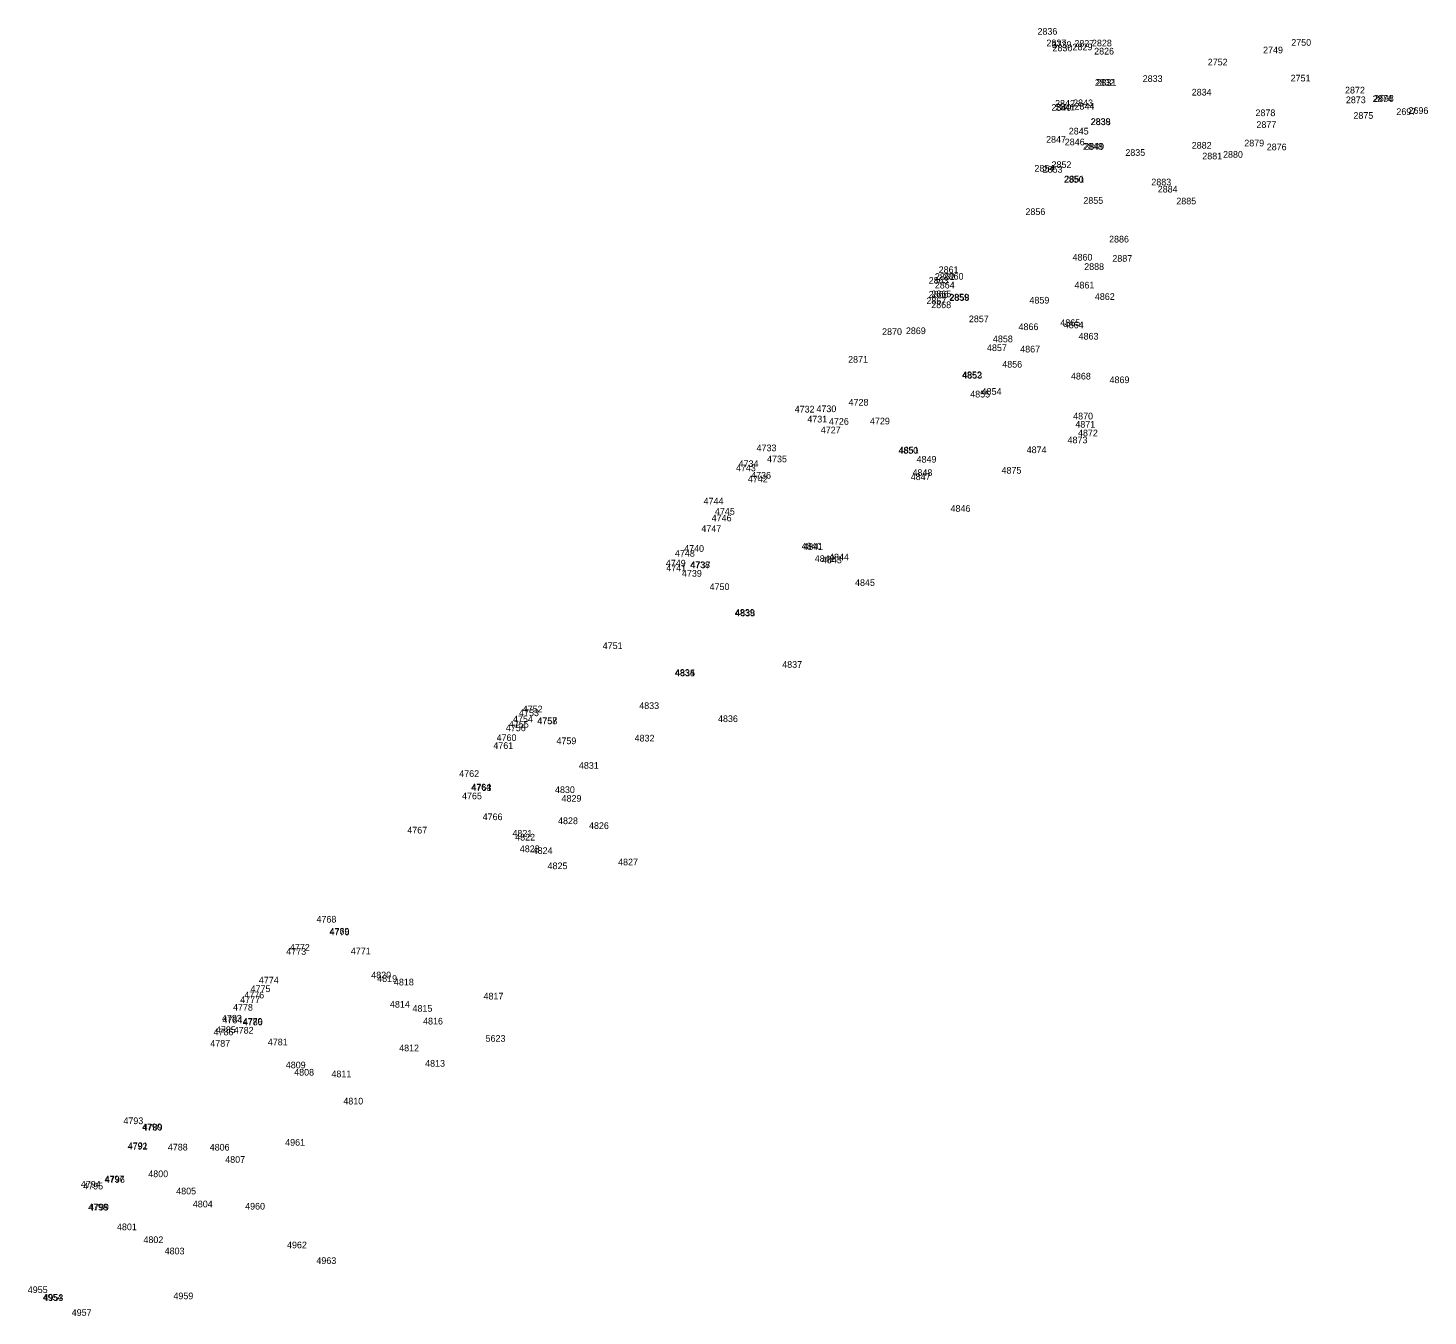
# Model space of a CAD drawing. Extents: x -740053 to -737517, y -1033516 to -1032476.
# Drawn here: x -738879 to -738763.6, y -1032731.7 to -1032625.6 of the extents above; entities that cross this region are included whole.
import ezdxf

# ---------------------------------------------------------------- set-up
doc = ezdxf.new("R2010")
doc.units = 0
doc.layers.add('bod-cislo', color=7, linetype='Continuous')

msp = doc.modelspace()

# ---------------------------------------------------------------- texts
at = {"layer": 'bod-cislo'}
for s, p in [('2836', (-738795.8, -1032626.13)), ('2837', (-738795.06, -1032627.08)), ('3739', (-738794.63, -1032627.22)), ('2830', (-738794.56, -1032627.49)), ('2829', (-738792.91, -1032627.41)), ('2827', (-738792.76, -1032627.12)), ('2828', (-738791.31, -1032627.09)), ('2826', (-738791.13, -1032627.76)), ('2749', (-738777.21, -1032627.66)), ('2750', (-738774.89, -1032627.04)), ('2752', (-738781.77, -1032628.66)), ('2833', (-738787.13, -1032630.02)), ('2751', (-738774.94, -1032629.98)), ('2832', (-738791.07, -1032630.33)), ('2831', (-738790.94, -1032630.34)), ('2834', (-738783.09, -1032631.14)), ('2872', (-738770.46, -1032630.97)), ('2840', (-738794.65, -1032632.4)), ('2842', (-738794.35, -1032632.06)), ('2841', (-738794.33, -1032632.36)), ('2843', (-738792.86, -1032632.02)), ('2844', (-738792.75, -1032632.3)), ('2873', (-738770.39, -1032631.77)), ('2874', (-738768.19, -1032631.68)), ('2698', (-738768.08, -1032631.64)), ('2839', (-738791.42, -1032633.56)), ('2838', (-738791.4, -1032633.58)), ('2878', (-738777.84, -1032632.84)), ('2875', (-738769.77, -1032633.06)), ('2697', (-738766.23, -1032632.74)), ('2696', (-738765.23, -1032632.65)), ('2845', (-738793.22, -1032634.35)), ('2877', (-738777.76, -1032633.81)), ('2847', (-738795.09, -1032635.03)), ('2846', (-738793.55, -1032635.24)), ('2848', (-738792.05, -1032635.6)), ('2849', (-738791.95, -1032635.61)), ('2882', (-738783.09, -1032635.52)), ('2879', (-738778.76, -1032635.33)), ('2876', (-738776.91, -1032635.65)), ('2852', (-738794.64, -1032637.11)), ('2835', (-738788.56, -1032636.11)), ('2881', (-738782.22, -1032636.4)), ('2880', (-738780.51, -1032636.27)), ('2854', (-738796.05, -1032637.41)), ('2853', (-738795.37, -1032637.5)), ('2850', (-738793.63, -1032638.33)), ('2851', (-738793.58, -1032638.29)), ('2883', (-738786.42, -1032638.54)), ('2884', (-738785.89, -1032639.13)), ('2855', (-738792.02, -1032640.06)), ('2885', (-738784.36, -1032640.11)), ('2856', (-738796.79, -1032640.99)), ('2886', (-738789.9, -1032643.25)), ('4860', (-738792.91, -1032644.74)), ('2887', (-738789.63, -1032644.84)), ('2862', (-738804.25, -1032646.33)), ('2861', (-738803.94, -1032645.77)), ('2860', (-738803.53, -1032646.31)), ('2888', (-738791.95, -1032645.51)), ('2863', (-738804.76, -1032646.65)), ('2864', (-738804.26, -1032647.04)), ('4861', (-738792.75, -1032647.04)), ('2867', (-738804.95, -1032648.33)), ('2866', (-738804.76, -1032647.79)), ('2868', (-738804.55, -1032648.66)), ('2865', (-738804.54, -1032647.76)), ('2859', (-738803.08, -1032648.03)), ('2858', (-738803.04, -1032648.06)), ('4859', (-738796.46, -1032648.28)), ('4862', (-738791.07, -1032647.98)), ('2857', (-738801.45, -1032649.82)), ('2870', (-738808.6, -1032650.87)), ('2869', (-738806.64, -1032650.8)), ('4866', (-738797.36, -1032650.47)), ('4865', (-738793.92, -1032650.13)), ('4864', (-738793.63, -1032650.32)), ('4857', (-738799.96, -1032652.2)), ('4858', (-738799.47, -1032651.47)), ('4863', (-738792.41, -1032651.25)), ('2871', (-738811.4, -1032653.16)), ('4867', (-738797.22, -1032652.31)), ('4852', (-738802.02, -1032654.43)), ('4853', (-738801.99, -1032654.47)), ('4856', (-738798.7, -1032653.56)), ('4868', (-738793.04, -1032654.54)), ('4869', (-738789.86, -1032654.84)), ('4728', (-738811.36, -1032656.69)), ('4855', (-738801.34, -1032656.02)), ('4854', (-738800.4, -1032655.8)), ('4732', (-738815.8, -1032657.26)), ('4730', (-738814.01, -1032657.23)), ('4870', (-738792.86, -1032657.83)), ('4731', (-738814.76, -1032658.08)), ('4727', (-738813.65, -1032658.97)), ('4726', (-738812.98, -1032658.27)), ('4729', (-738809.6, -1032658.24)), ('4871', (-738792.68, -1032658.51)), ('4873', (-738793.32, -1032659.8)), ('4872', (-738792.46, -1032659.22)), ('4733', (-738818.94, -1032660.45)), ('4735', (-738818.08, -1032661.36)), ('4850', (-738807.26, -1032660.66)), ('4851', (-738807.22, -1032660.63)), ('4849', (-738805.76, -1032661.39)), ('4874', (-738796.69, -1032660.61)), ('4743', (-738820.64, -1032662.1)), ('4734', (-738820.42, -1032661.75)), ('4848', (-738806.1, -1032662.49)), ('4875', (-738798.76, -1032662.3)), ('4742', (-738819.66, -1032663.01)), ('4736', (-738819.39, -1032662.71)), ('4847', (-738806.24, -1032662.83)), ('4744', (-738823.31, -1032664.84)), ('4745', (-738822.37, -1032665.68)), ('4846', (-738802.96, -1032665.44)), ('4747', (-738823.49, -1032667.1)), ('4746', (-738822.64, -1032666.23)), ('4748', (-738825.67, -1032669.14)), ('4740', (-738824.91, -1032668.74)), ('4840', (-738815.23, -1032668.55)), ('4841', (-738815.1, -1032668.59)), ('4844', (-738812.97, -1032669.45)), ('4749', (-738826.42, -1032669.95)), ('4741', (-738826.38, -1032670.34)), ('4738', (-738824.42, -1032670.08)), ('4737', (-738824.38, -1032670.1)), ('4842', (-738814.15, -1032669.57)), ('4843', (-738813.56, -1032669.68)), ('4739', (-738825.09, -1032670.79)), ('4845', (-738810.83, -1032671.55)), ('4750', (-738822.81, -1032671.89)), ('4839', (-738820.73, -1032674.01)), ('4838', (-738820.7, -1032674.06)), ('4751', (-738831.62, -1032676.75)), ('4837', (-738816.83, -1032678.3)), ('4834', (-738825.68, -1032678.96)), ('4835', (-738825.65, -1032679)), ('4752', (-738838.21, -1032681.97)), ('4833', (-738828.61, -1032681.69)), ('4755', (-738839.35, -1032683.23)), ('4754', (-738839.01, -1032682.8)), ('4753', (-738838.51, -1032682.28)), ('4757', (-738837.01, -1032682.93)), ('4758', (-738837, -1032682.95)), ('4836', (-738822.12, -1032682.77)), ('4760', (-738840.36, -1032684.33)), ('4756', (-738839.6, -1032683.52)), ('4832', (-738828.99, -1032684.37)), ('4761', (-738840.63, -1032684.98)), ('4759', (-738835.43, -1032684.59)), ('4831', (-738833.58, -1032686.62)), ('4762', (-738843.44, -1032687.29)), ('4764', (-738842.46, -1032688.4)), ('4763', (-738842.42, -1032688.45)), ('4830', (-738835.55, -1032688.62)), ('4765', (-738843.21, -1032689.13)), ('4829', (-738835.01, -1032689.33)), ('4766', (-738841.51, -1032690.85)), ('4828', (-738835.3, -1032691.18)), ('4767', (-738847.72, -1032691.95)), ('4821', (-738839.06, -1032692.21)), ('4822', (-738838.83, -1032692.53)), ('4826', (-738832.75, -1032691.58)), ('4823', (-738838.45, -1032693.49)), ('4824', (-738837.39, -1032693.64)), ('4827', (-738830.35, -1032694.58)), ('4825', (-738836.16, -1032694.89)), ('4768', (-738855.2, -1032699.29)), ('4769', (-738854.13, -1032700.28)), ('4770', (-738854.12, -1032700.34)), ('4772', (-738857.39, -1032701.61)), ('4773', (-738857.69, -1032701.94)), ('4771', (-738852.37, -1032701.91)), ('4820', (-738850.69, -1032703.89)), ('4775', (-738860.63, -1032705.02)), ('4774', (-738859.95, -1032704.31)), ('4819', (-738850.2, -1032704.18)), ('4818', (-738848.82, -1032704.47)), ('4777', (-738861.49, -1032705.92)), ('4776', (-738861.15, -1032705.54)), ('4814', (-738849.15, -1032706.3)), ('4817', (-738841.44, -1032705.63)), ('4783', (-738862.99, -1032707.45)), ('4778', (-738862.08, -1032706.55)), ('4815', (-738847.29, -1032706.64)), ('4786', (-738863.68, -1032708.58)), ('4785', (-738863.49, -1032708.4)), ('4784', (-738862.95, -1032707.59)), ('4782', (-738862.02, -1032708.44)), ('4779', (-738861.28, -1032707.7)), ('4780', (-738861.27, -1032707.76)), ('4816', (-738846.42, -1032707.69)), ('4787', (-738863.95, -1032709.52)), ('4781', (-738859.21, -1032709.41)), ('5623', (-738841.27, -1032709.11)), ('4812', (-738848.39, -1032709.9)), ('4809', (-738857.73, -1032711.3)), ('4808', (-738857.04, -1032711.9)), ('4811', (-738853.97, -1032712.04)), ('4813', (-738846.25, -1032711.17)), ('4810', (-738852.99, -1032714.28)), ('4793', (-738871.11, -1032715.9)), ('4790', (-738869.58, -1032716.4)), ('4789', (-738869.52, -1032716.43)), ('4791', (-738870.74, -1032717.95)), ('4961', (-738857.78, -1032717.68)), ('4792', (-738870.77, -1032718)), ('4788', (-738867.45, -1032718.07)), ('4806', (-738864, -1032718.08)), ('4807', (-738862.72, -1032719.09)), ('4794', (-738874.62, -1032721.13)), ('4795', (-738874.42, -1032721.28)), ('4797', (-738872.67, -1032720.69)), ('4796', (-738872.63, -1032720.74)), ('4800', (-738869.06, -1032720.27)), ('4805', (-738866.76, -1032721.69)), ('4798', (-738874.02, -1032723.01)), ('4799', (-738873.94, -1032723.02)), ('4804', (-738865.39, -1032722.76)), ('4960', (-738861.08, -1032722.94)), ('4801', (-738871.64, -1032724.64)), ('4802', (-738869.46, -1032725.7)), ('4803', (-738867.71, -1032726.63)), ('4962', (-738857.63, -1032726.13)), ('4963', (-738855.21, -1032727.42)), ('4955', (-738878.99, -1032729.82)), ('4954', (-738877.76, -1032730.44)), ('4953', (-738877.7, -1032730.47)), ('4959', (-738866.99, -1032730.33)), ('4957', (-738875.37, -1032731.7))]:
    msp.add_text(s, height=0.55, dxfattribs=at).set_placement(p)

doc.saveas('drawing.dxf')
